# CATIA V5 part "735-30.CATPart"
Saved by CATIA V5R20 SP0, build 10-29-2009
Part number: 735-30
Bounding box of the stored display mesh (mm): x -28 to 28, y -28 to 28, z -30 to 45
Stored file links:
  C:\Users\Utente\Desktop\IO LAVORO\3D X SITO CF\X SITO\735\735-30.CATPart
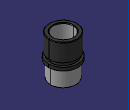
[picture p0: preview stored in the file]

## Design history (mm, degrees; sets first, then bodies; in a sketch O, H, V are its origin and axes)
Set1
  DatumSurface1 to DatumSurface25 "735-30"
Body1 (main body)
